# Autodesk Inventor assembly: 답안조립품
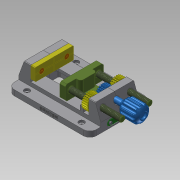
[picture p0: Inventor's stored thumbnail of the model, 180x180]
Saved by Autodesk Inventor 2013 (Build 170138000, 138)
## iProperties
Created: 2018-03
Part Number: 답안조립품
Document SubType Name: Assembly
Designer: Administrator
Mass: 1443.92 g
Surface Area: 918.51 cm^2
Volume: 340.422 cm^3
Density: 4.24157 g/cm^3
Author: Administrator
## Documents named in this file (10)
- C:\Users\Administrator\Desktop\380308V1009\답안조립품.iam
- C:\Users\Administrator\Desktop\380308V1009\바이스본체 A.ipt
- C:\Users\Administrator\Desktop\380308V1009\바이스본체 B.ipt
- C:\Users\Administrator\Desktop\380308V1009\고정 플레이트.ipt
- C:\Users\Administrator\Desktop\380308V1009\십자오목머리나사 M3.ipt
- C:\Users\Administrator\Desktop\380308V1009\지지대.ipt
- C:\Users\Administrator\Desktop\380308V1009\십자오목머리나사 M4.ipt
- C:\Users\Administrator\Desktop\380308V1009\핸들.ipt
- C:\Users\Administrator\Desktop\380308V1009\슬라이딩 부품.ipt
- C:\Users\Administrator\Desktop\380308V1009\스퍼기어.ipt
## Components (3 placed, 2 different names)
1. 고정 플레이트:1
2. 고정 플레이트:2
3. 핸들:1
